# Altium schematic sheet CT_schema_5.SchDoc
size 556 x 419 mm
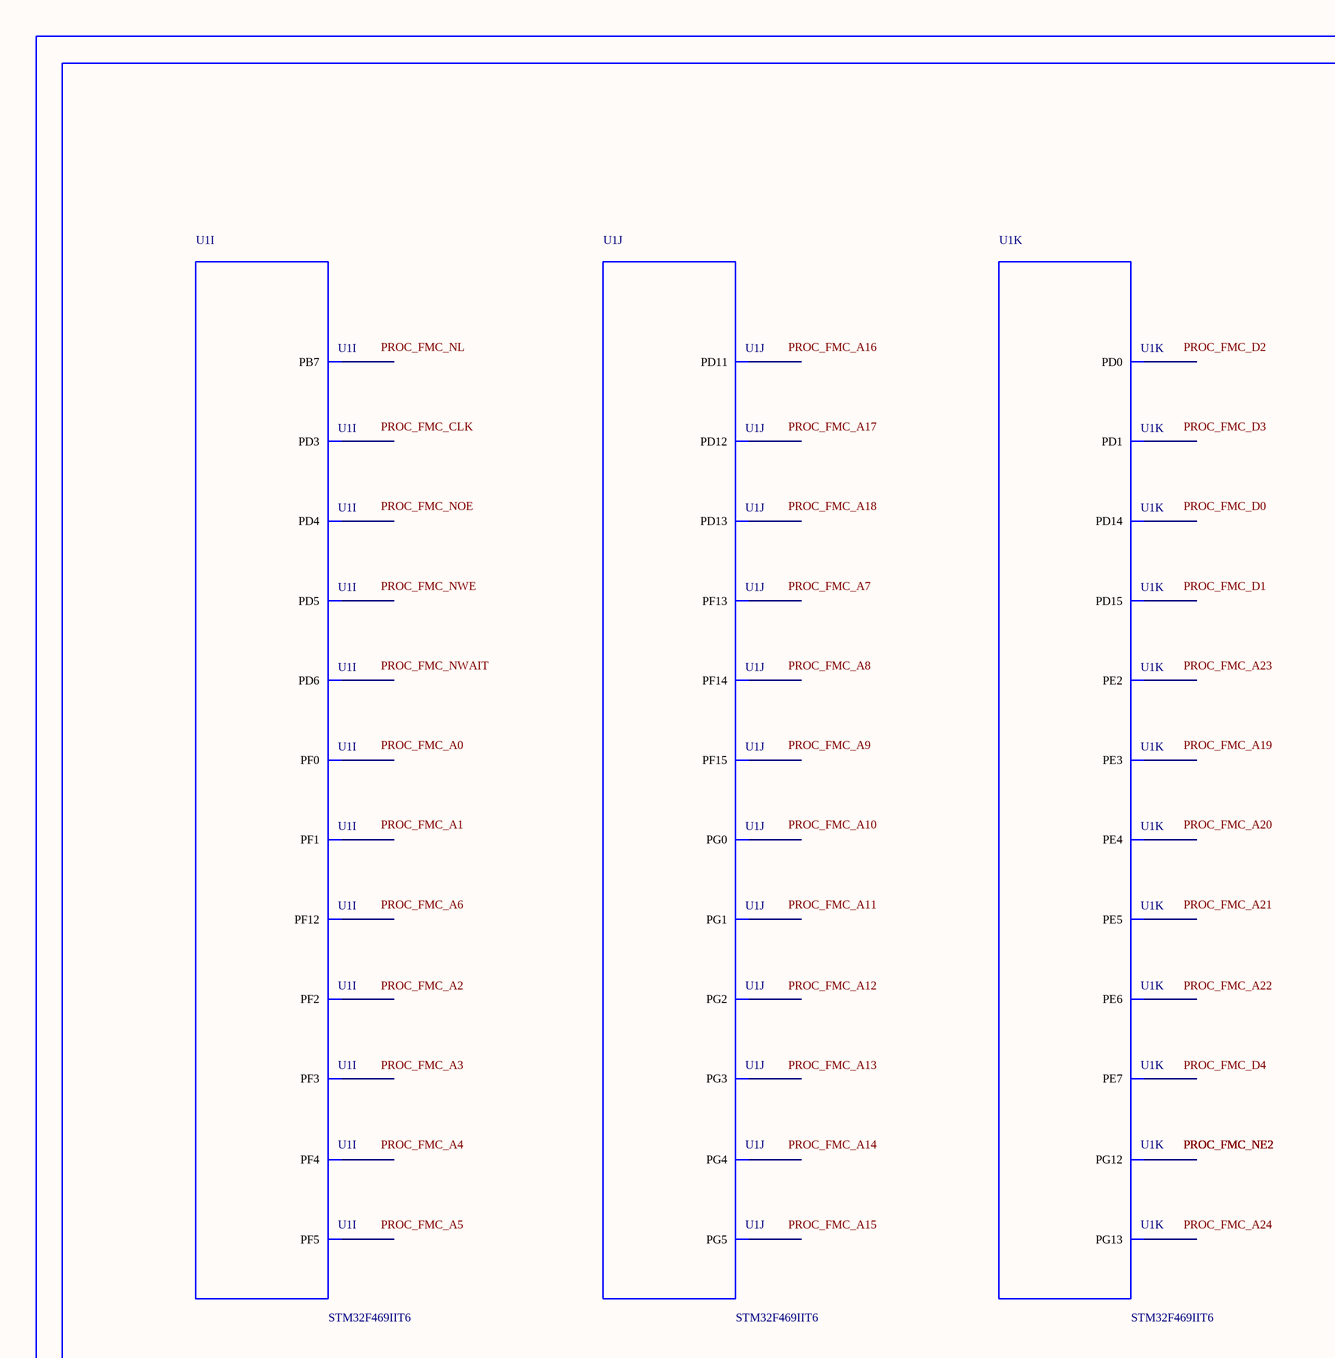
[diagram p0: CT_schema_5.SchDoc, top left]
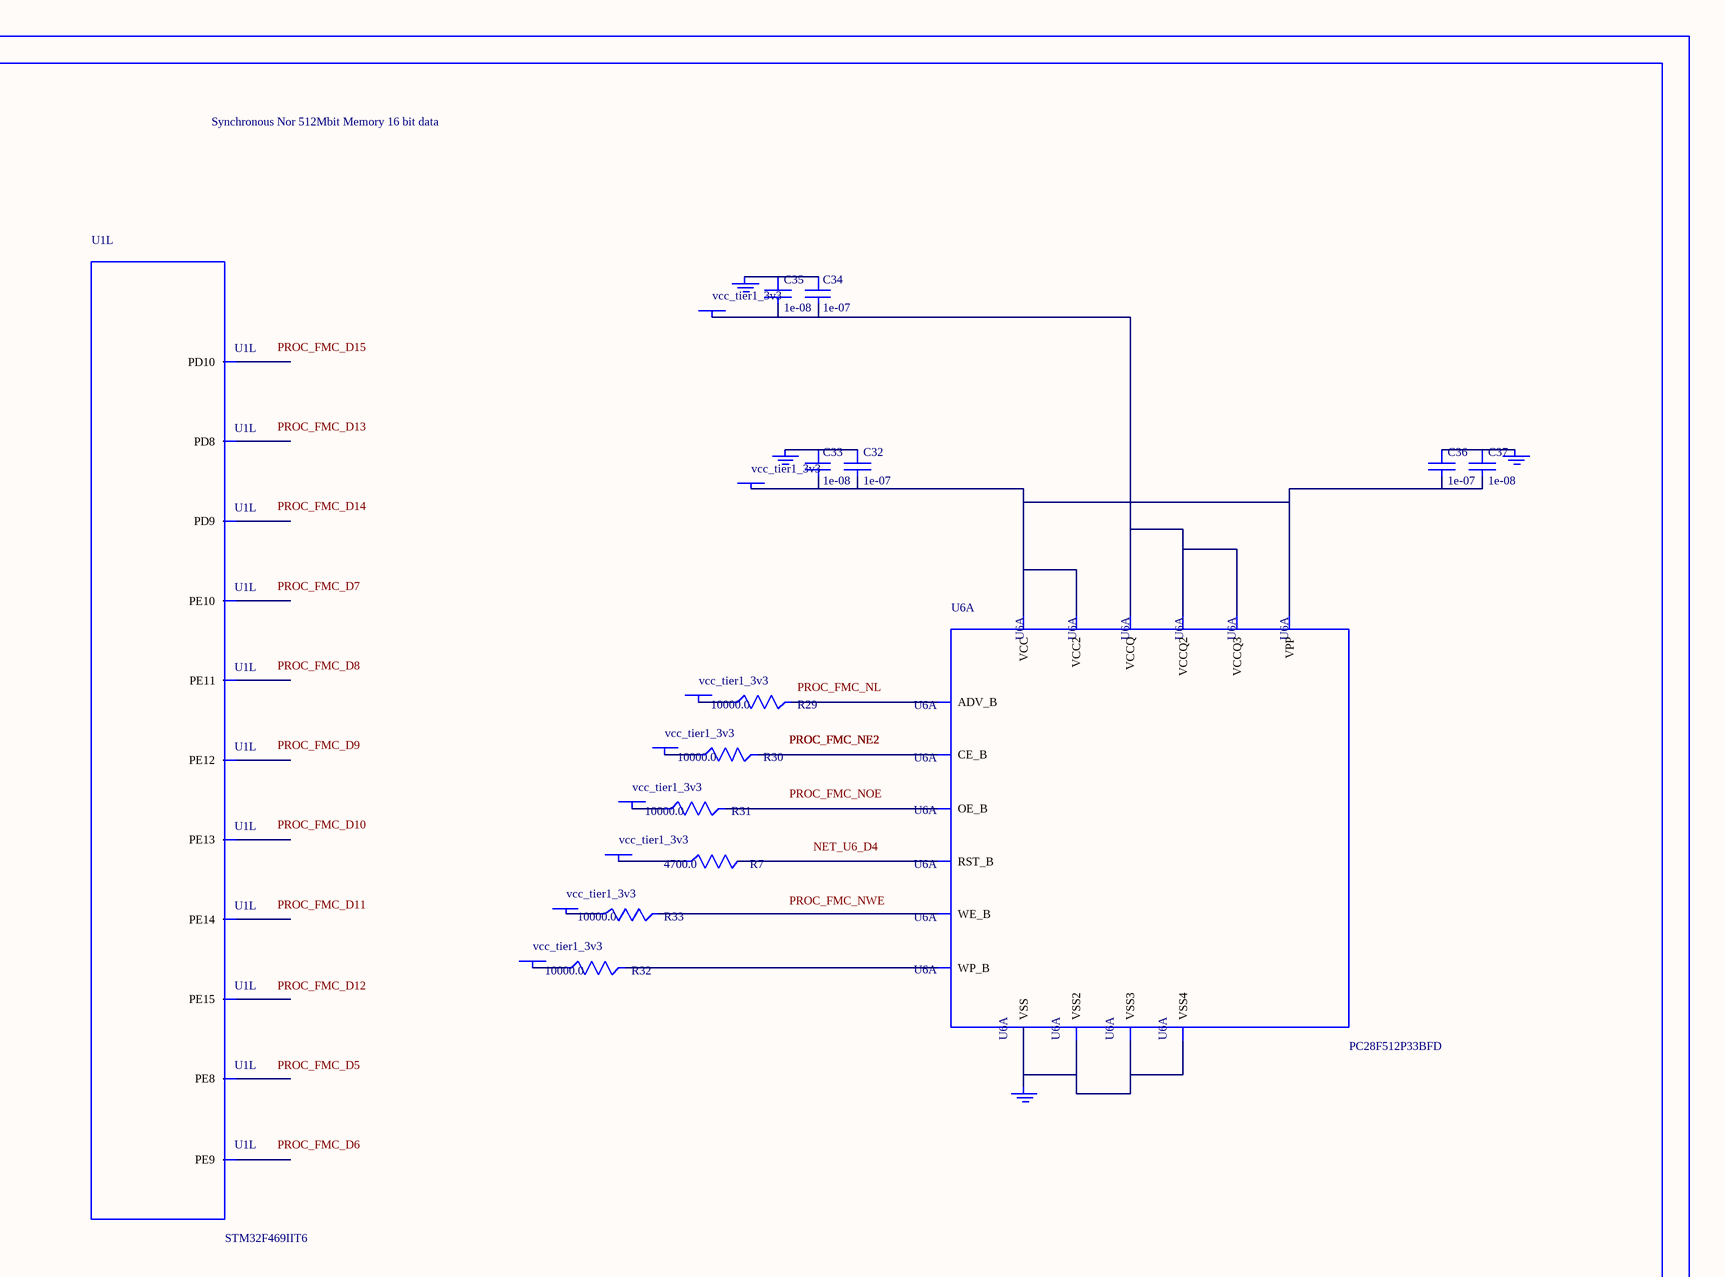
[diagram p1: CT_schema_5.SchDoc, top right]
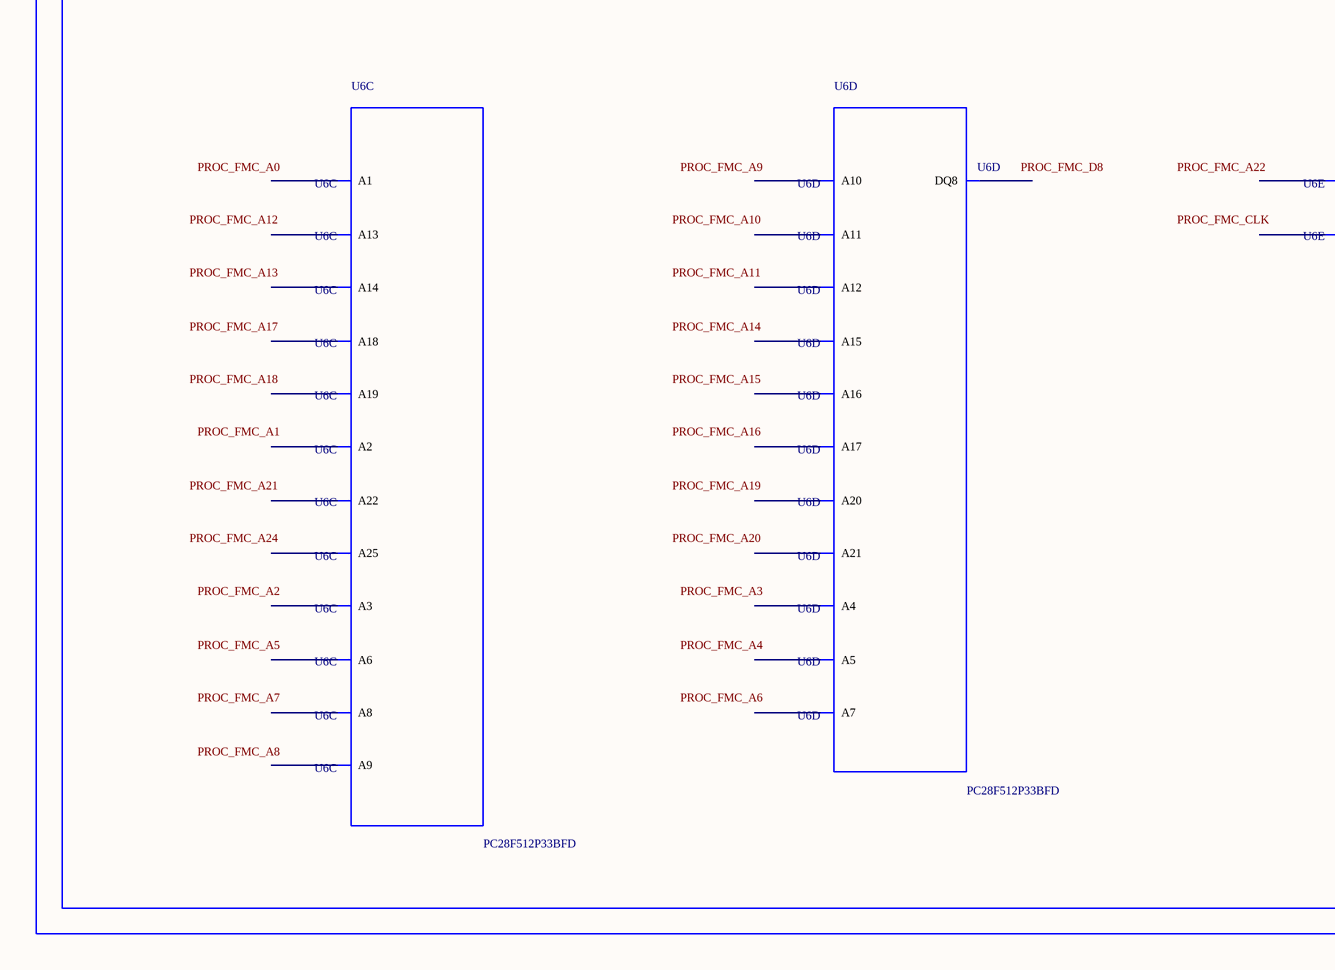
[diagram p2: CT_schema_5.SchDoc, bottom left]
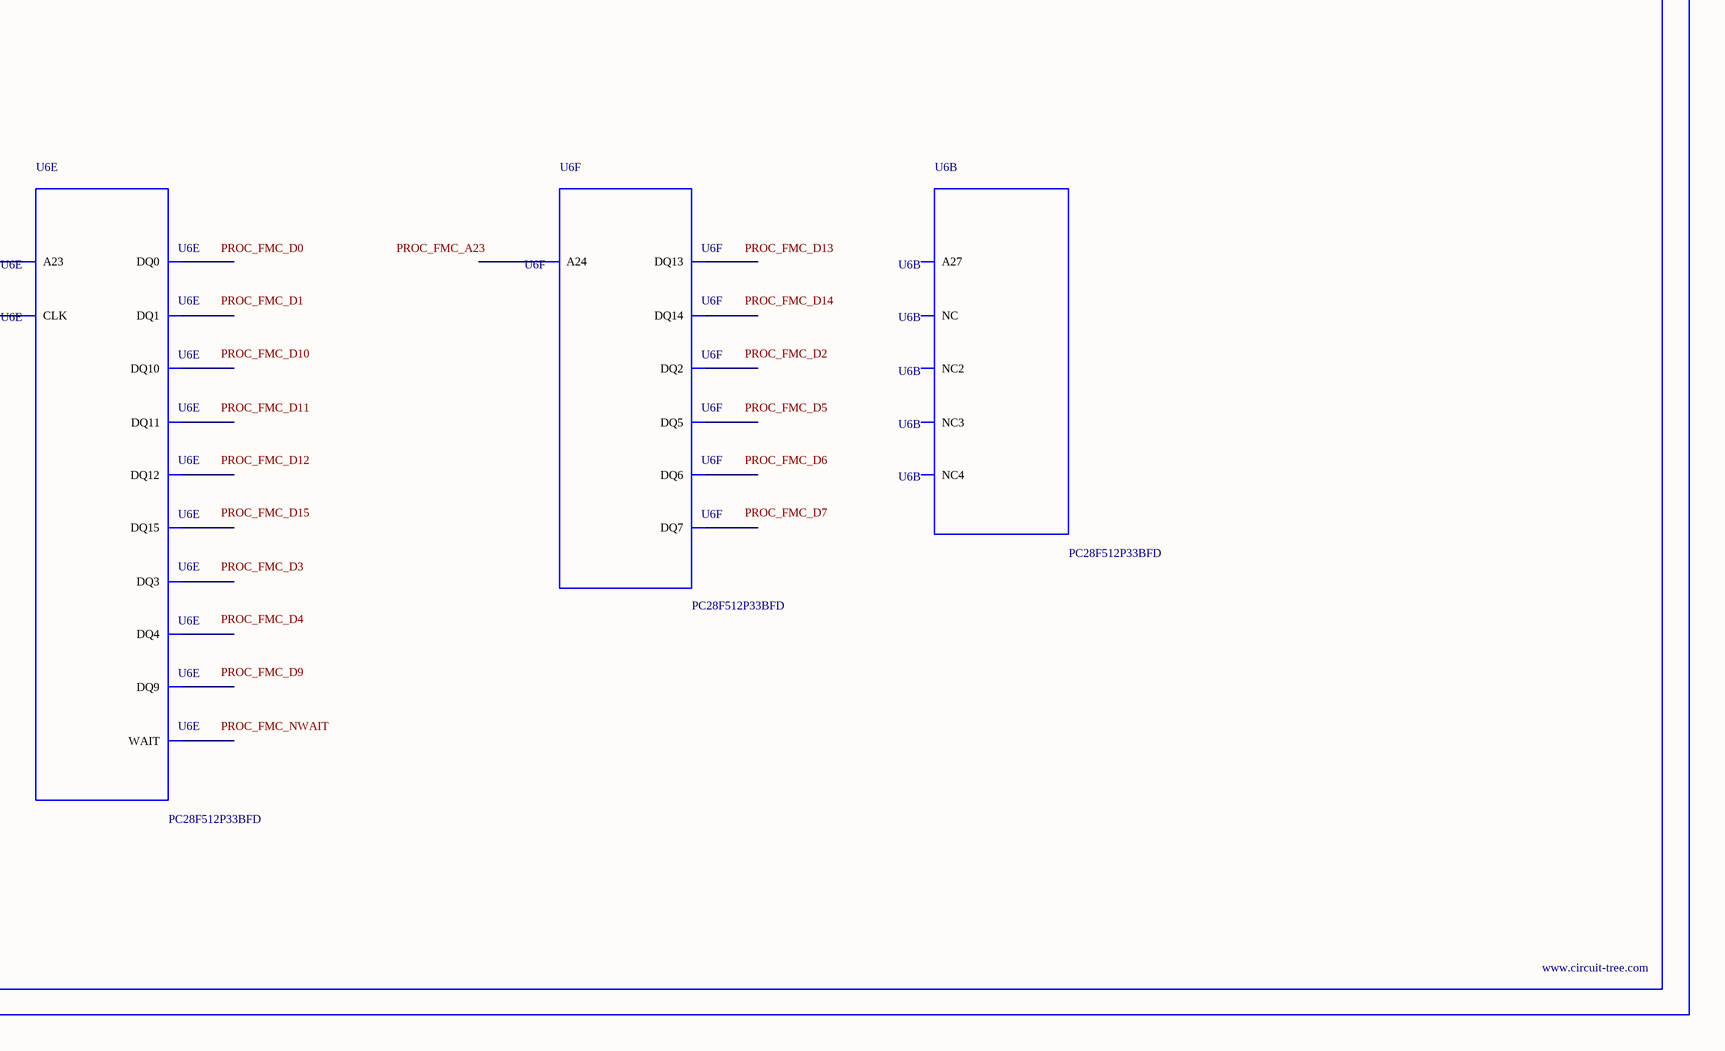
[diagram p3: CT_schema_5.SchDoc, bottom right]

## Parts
BORDER4  (no value)
C32  1e-07  [C0402]
C33  1e-08  [C0402]
C34  1e-07  [C0402]
C35  1e-08  [C0402]
C36  1e-07  [C0402]
C37  1e-08  [C0402]
GND_INSTANCE_4_0  (no value)
GND_INSTANCE_4_1  (no value)
GND_INSTANCE_4_2  (no value)
GND_INSTANCE_4_3  (no value)
POWER_INSTANCE_4_0  vcc_tier1_3v3
POWER_INSTANCE_4_1  vcc_tier1_3v3
POWER_INSTANCE_4_2  vcc_tier1_3v3
POWER_INSTANCE_4_3  vcc_tier1_3v3
POWER_INSTANCE_4_4  vcc_tier1_3v3
POWER_INSTANCE_4_5  vcc_tier1_3v3
POWER_INSTANCE_4_6  vcc_tier1_3v3
POWER_INSTANCE_4_7  vcc_tier1_3v3
R7  4700.0  [R0603]
R29  10000.0  [R0603]
R30  10000.0  [R0603]
R31  10000.0  [R0603]
R32  10000.0  [R0603]
R33  10000.0  [R0603]
U1  STM32F469IIT6  [LQFP176]  (parts I,J,K,L of 14)
U6  PC28F512P33BFD  [PC28F512P33BFD]  (parts A,B,C,D,E,F of 6)

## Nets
NetC32_1: C32.1 C33.1 GND_INSTANCE_4_0.0(GND)
NetC32_2: C32.2 C33.2 C36.2 C37.2 POWER_INSTANCE_4_0.0(PWR) U6.A4(VPP) U6.A6(VCC) U6.H3(VCC2)
NetC34_1: C34.1 C35.1 GND_INSTANCE_4_1.0(GND)
NetC34_2: C34.2 C35.2 POWER_INSTANCE_4_1.0(PWR) U6.D5(VCCQ) U6.D6(VCCQ2) U6.G4(VCCQ3)
NetC36_1: C36.1 C37.1 GND_INSTANCE_4_2.0(GND)
NetGND_INSTANCE_4_3_0: GND_INSTANCE_4_3.0(GND) U6.B2(VSS) U6.H2(VSS2) U6.H4(VSS3) U6.H6(VSS4)
NetPOWER_INSTANCE_4_2_0: POWER_INSTANCE_4_2.0(PWR) R29.1
NetPOWER_INSTANCE_4_3_0: POWER_INSTANCE_4_3.0(PWR) R30.1
NetPOWER_INSTANCE_4_4_0: POWER_INSTANCE_4_4.0(PWR) R31.1
NetPOWER_INSTANCE_4_5_0: POWER_INSTANCE_4_5.0(PWR) R32.1
NetPOWER_INSTANCE_4_6_0: POWER_INSTANCE_4_6.0(PWR) R33.1
NetPOWER_INSTANCE_4_7_0: POWER_INSTANCE_4_7.0(PWR) R7.1
NetR7_2: R7.2 U6.D4(RST_B)
NetR29_2: R29.2 U6.F6(ADV_B)
NetR30_2: R30.2 U6.B4(CE_B)
NetR31_2: R31.2 U6.F8(OE_B)
NetR32_2: R32.2 U6.C6(WP_B)
NetR33_2: R33.2 U6.G8(WE_B)

Not connected (* = marked no-connect by the designer): U1 1(PE2) 2(PE3) 3(PE4) 4(PE5) 5(PE6) 16(PF0) 17(PF1) 18(PF2) 19(PF3) 20(PF4) 21(PF5) 60(PF12) 63(PF13) 64(PF14) 65(PF15) 66(PG0) 67(PG1) 68(PE7) 69(PE8) 70(PE9) 73(PE10) 74(PE11) 75(PE12) 76(PE13) 77(PE14) 78(PE15) 89(PD8) 90(PD9) 91(PD10) 92(PD11) 93(PD12) 94(PD13) 97(PD14) 98(PD15) 110(PG2) 111(PG3) 112(PG4) 113(PG5) 142(PD0) 143(PD1) 145(PD3) 146(PD4) 147(PD5) 150(PD6) 155(PG12) 156(PG13) 165(PB7); U6 A1 A2(A6) A3(A8) A5(A13) A7(A18) A8(A22) B1(A2) B3(A9) B5(A14) B6(A25) B7(A19) B8(NC) C1(A3) C2(A7) C3(A10) C4(A12) C5(A15) C7(A20) C8(A21) D1(A4) D2(A5) D3(A11) D7(A16) D8(A17) E1(DQ8) E2(DQ1) E3(DQ9) E4(DQ3) E5(DQ4) E6(CLK) E7(DQ15) E8(NC2) F1(NC3) F2(DQ0) F3(DQ10) F4(DQ11) F5(DQ12) F7(WAIT) G1(A23) G2(NC4) G3(DQ2) G5(DQ5) G6(DQ6) G7(DQ14) H1(A27) H5(DQ13) H7(DQ7) H8(A24)

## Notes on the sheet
- Labels drawn without touching a wire or pin: NET_U6_D4, PROC_FMC_A0, PROC_FMC_A1, PROC_FMC_A2, PROC_FMC_A3, PROC_FMC_A4, PROC_FMC_A5, PROC_FMC_A6, PROC_FMC_A7, PROC_FMC_A8, PROC_FMC_A9, PROC_FMC_A10, PROC_FMC_A11, PROC_FMC_A12, PROC_FMC_A13, PROC_FMC_A14, PROC_FMC_A15, PROC_FMC_A16, PROC_FMC_A17, PROC_FMC_A18, PROC_FMC_A19, PROC_FMC_A20, PROC_FMC_A21, PROC_FMC_A22, PROC_FMC_A23, PROC_FMC_A24, PROC_FMC_CLK, PROC_FMC_D0, PROC_FMC_D1, PROC_FMC_D2, PROC_FMC_D3, PROC_FMC_D4, PROC_FMC_D5, PROC_FMC_D6, PROC_FMC_D7, PROC_FMC_D8, PROC_FMC_D9, PROC_FMC_D10, PROC_FMC_D11, PROC_FMC_D12, PROC_FMC_D13, PROC_FMC_D14, PROC_FMC_D15, PROC_FMC_NL, PROC_FMC_NOE, PROC_FMC_NWAIT, PROC_FMC_NWE

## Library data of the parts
BORDER4 = BORDER_PAGE4
C32 C34 C36 = C0402C104K3RACTU
C33 C35 C37 = C0402C103K3RAC
GND_INSTANCE_4_0-GND_INSTANCE_4_3 = GND
POWER_INSTANCE_4_0-POWER_INSTANCE_4_7 = PWR
R7 = RC0603JR-074K7L
R29-R33 = RC0603JR-0710KL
